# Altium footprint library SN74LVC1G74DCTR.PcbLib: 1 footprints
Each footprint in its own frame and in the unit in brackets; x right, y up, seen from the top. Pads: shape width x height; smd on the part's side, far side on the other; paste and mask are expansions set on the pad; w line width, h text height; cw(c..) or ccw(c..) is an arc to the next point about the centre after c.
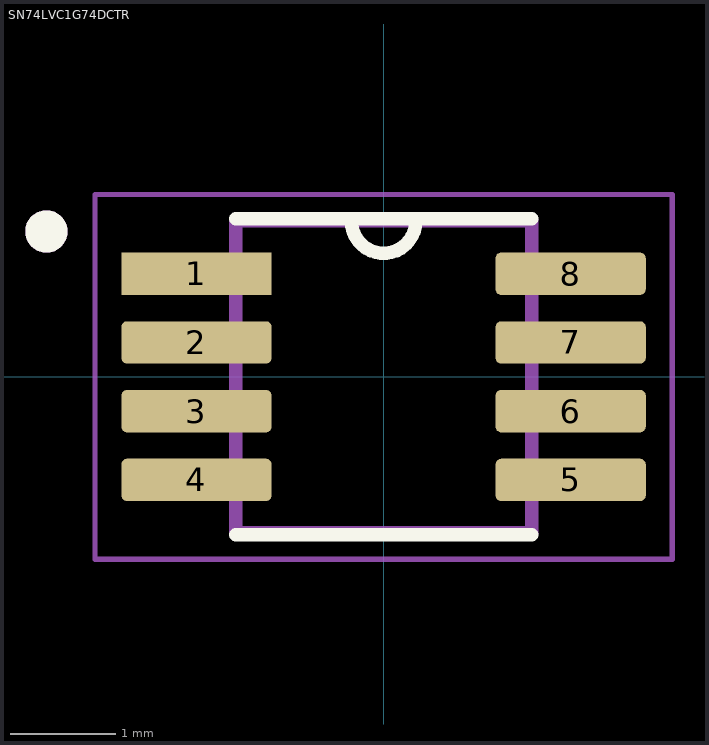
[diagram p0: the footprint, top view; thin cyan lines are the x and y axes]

## SN74LVC1G74DCTR [mm]
pads (8):
  rect 1.42x0.4 smd: 1(-1.77,0.975)
  rrect25% 1.42x0.4 smd: 2(-1.77,0.325) 3(-1.77,-0.325) 4(-1.77,-0.975) 5(1.77,-0.975) 6(1.77,-0.325) 7(1.77,0.325) 8(1.77,0.975)
Top Overlay:
  circle w0.2: c-3.19,1.375 r0.1
  lines w0.127: -1.4,-1.495 1.4,-1.495 ; -1.4,1.495 1.4,1.495 ; -0.305,1.473 ccw(c0,1.473) 0.305,1.473
Mechanical 13:
  circle w0.2: c-3.19,1.375 r0.1
  lines w0.127: -1.4,-1.475 1.4,-1.475 1.4,1.475 -1.4,1.475 -1.4,-1.475
Mechanical 15:
  lines w0.05: -2.73,-1.725 2.73,-1.725 2.73,1.725 -2.73,1.725 -2.73,-1.725
3D body "step_temp.STEP": height 1.3, standoff 0, extent -2,-1.5 2,1.45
